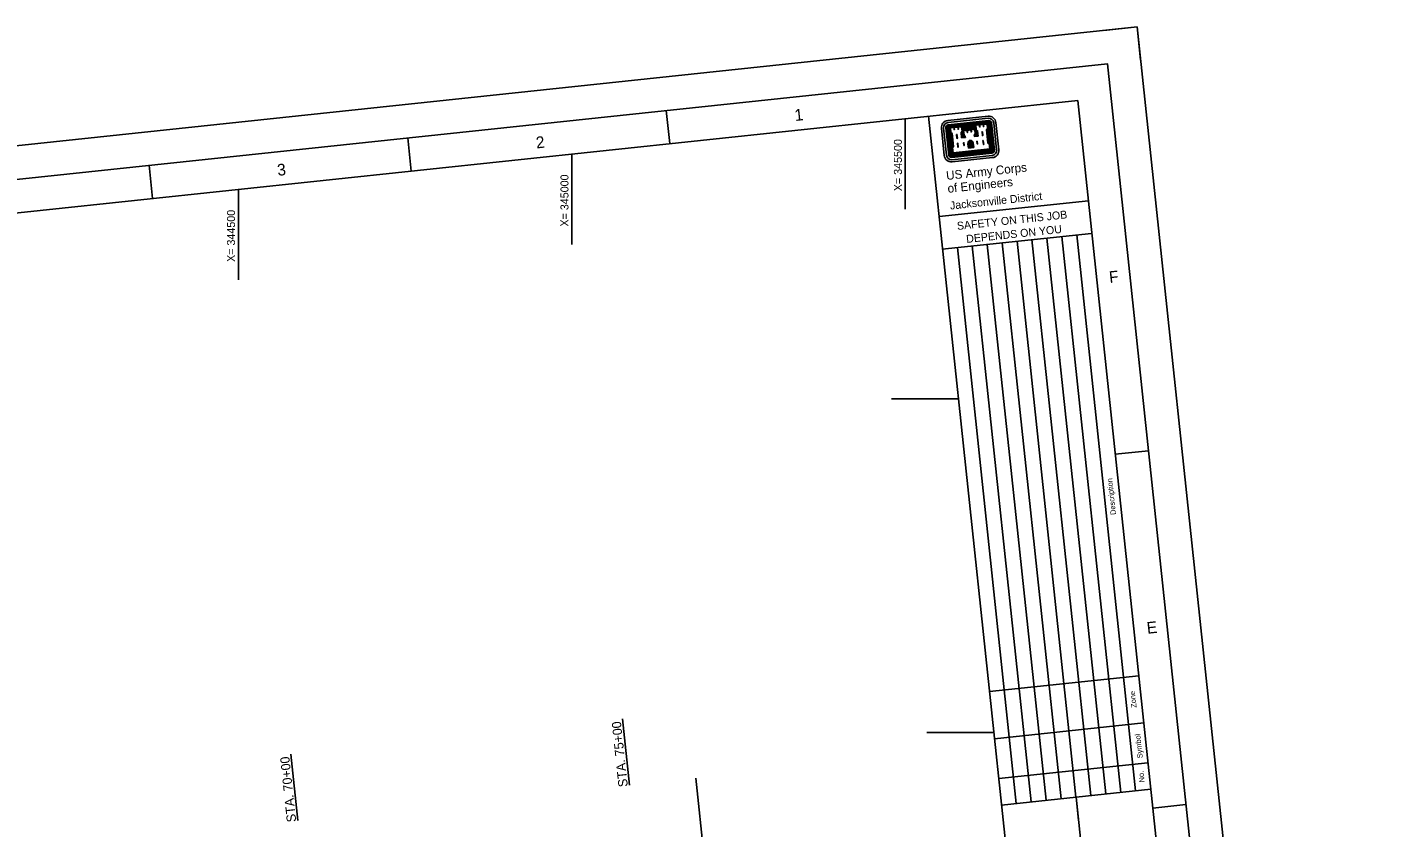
# Model space of a CAD drawing. Extents: x 341472 to 346206, y 1184213 to 1188058.
# Drawn here: x 344183 to 346206, y 1186858 to 1188058 of the extents above; entities that cross this region are included whole.
import ezdxf

# ---------------------------------------------------------------- set-up
doc = ezdxf.new("R2010")
doc.units = 0
for name, color, linetype in [('G-ANNO-NPLT', 7, 'Continuous'), ('G-ANNO-TEXT-LOGO', 7, 'Continuous'), ('G-ANNO-TEXT-TTLB', 7, 'Continuous'), ('G-ANNO-TTLB', 7, 'Continuous'), ('V-ALGN-TEXT', 7, 'Continuous'), ('V-ANNO-MATC', 7, 'Continuous'), ('V-TOPO-COOR-STAT', 7, 'Continuous')]:
    doc.layers.add(name, color=color, linetype=linetype)

msp = doc.modelspace()

# ---------------------------------------------------------------- linework, layer by layer
at = {"layer": 'G-ANNO-NPLT'}
msp.add_lwpolyline([(341472, 1187593.7), (345847.5, 1188057.5), (346205.9, 1184676.5), (341830.4, 1184212.7)], close=True, dxfattribs=at)
msp.add_lwpolyline([(345852.7, 1188007.8), (345847.5, 1188057.5), (345797.8, 1188052.2)], dxfattribs=at)
at = {"layer": 'G-ANNO-TEXT-LOGO'}
for p, q in [((345624.2, 1187923.8), (345563.7, 1187917.4)), ((345564.1, 1187914.2), (345624.5, 1187920.7)), ((345624.9, 1187917.3), (345564.4, 1187910.9)), ((345625, 1187916.4), (345564.5, 1187910)), ((345625.1, 1187915.5), (345564.6, 1187909.1)), ((345625.1, 1187914.7), (345564.7, 1187908.3)), ((345625.2, 1187913.8), (345564.8, 1187907.4)), ((345624.1, 1187913.1), (345628.3, 1187873.5)), ((345624.9, 1187913.2), (345629.2, 1187872.7)), ((345625.8, 1187913.3), (345630.1, 1187872.5)), ((345626.7, 1187913.3), (345631, 1187872.6)), ((345627.5, 1187913.4), (345631.8, 1187872.7)), ((345628.4, 1187913.5), (345632.7, 1187872.8)), ((345629.3, 1187913.6), (345633.6, 1187872.8)), ((345632.7, 1187914), (345637, 1187873.2)), ((345640.3, 1187873.6), (345635.9, 1187914.3)), ((345554.2, 1187905.7), (345558.5, 1187864.9)), ((345561.7, 1187865.2), (345557.4, 1187906)), ((345560.9, 1187906.4), (345565.2, 1187865.6)), ((345561.8, 1187906.5), (345566.1, 1187865.7)), ((345562.6, 1187906.5), (345566.9, 1187865.8)), ((345563.5, 1187906.6), (345567.8, 1187865.9)), ((345564.3, 1187906.7), (345568.7, 1187866)), ((345565.2, 1187906.8), (345569.5, 1187866.4)), ((345566, 1187906.9), (345570.2, 1187867.3)), ((345567.7, 1187898.3), (345569.9, 1187877.5)), ((345568.6, 1187897.5), (345570.7, 1187878.5)), ((345585.8, 1187908.8), (345604.3, 1187910.8)), ((345585.9, 1187907.9), (345604.4, 1187909.9)), ((345586, 1187907.1), (345604.5, 1187909.1)), ((345586.1, 1187906.2), (345604.6, 1187908.2)), ((345586.2, 1187905.3), (345604.7, 1187907.3)), ((345586.3, 1187904.5), (345604.8, 1187906.5)), ((345586.4, 1187903.6), (345604.9, 1187905.6)), ((345623.5, 1187903.4), (345625.5, 1187884.4)), ((345624.3, 1187904.2), (345626.5, 1187883.6)), ((345629.7, 1187871.8), (345569.2, 1187865.4)), ((345629.8, 1187871), (345569.3, 1187864.6)), ((345629.2, 1187872.7), (345569.5, 1187866.4)), ((345628.3, 1187873.5), (345570.2, 1187867.3)), ((345594.7, 1187875.9), (345594, 1187882.5)), ((345594.7, 1187875.9), (345602.6, 1187876.7)), ((345595.5, 1187875.9), (345594.8, 1187882.6)), ((345596.4, 1187876), (345595.7, 1187882.7)), ((345597.3, 1187876.1), (345596.6, 1187882.8)), ((345598.1, 1187876.2), (345597.3, 1187882.9)), ((345599.2, 1187876.3), (345598.5, 1187883)), ((345600, 1187876.4), (345599.3, 1187883.1)), ((345600.9, 1187876.5), (345600.2, 1187883.2)), ((345601.8, 1187876.6), (345601.1, 1187883.3)), ((345602.6, 1187876.7), (345601.9, 1187883.4)), ((345629.9, 1187870.1), (345569.4, 1187863.7)), ((345630, 1187869.2), (345569.5, 1187862.8)), ((345630.1, 1187868.4), (345569.6, 1187862)), ((345630.4, 1187865), (345570, 1187858.6)), ((345570.3, 1187855.3), (345630.8, 1187861.7))]:
    msp.add_line(p, q, dxfattribs=at)
for points in [[(345566.7, 1187907), (345567.6, 1187899.1), (345569.4, 1187897.6), (345571.5, 1187878.6), (345570, 1187876.7), (345570.9, 1187868), (345627.5, 1187874), (345626.6, 1187882.7), (345624.7, 1187884.3), (345622.6, 1187903.3), (345624.3, 1187905.1), (345623.4, 1187913), (345616, 1187912.2), (345610.2, 1187911.6), (345604.8, 1187911), (345605.7, 1187903.2), (345607.7, 1187901.7), (345608.5, 1187894.7), (345604.3, 1187894.3), (345604.2, 1187895), (345605.8, 1187897), (345605, 1187904.7), (345597.5, 1187903.9), (345591.8, 1187903.3), (345586.5, 1187902.7), (345587.3, 1187895), (345589.3, 1187893.4), (345589.4, 1187892.7), (345585.2, 1187892.3), (345584.5, 1187899.2), (345586.1, 1187901.1), (345585.2, 1187908.9), (345577.8, 1187908.2), (345572, 1187907.5), (345566.7, 1187907)], [(345567.6, 1187906.2), (345568.3, 1187899.6), (345570.3, 1187898), (345572.4, 1187878.3), (345570.8, 1187876.3), (345571.6, 1187869), (345626.7, 1187874.8), (345625.9, 1187882.2), (345623.8, 1187883.8), (345621.7, 1187903.5), (345623.4, 1187905.5), (345622.7, 1187912), (345617.3, 1187911.4), (345617.7, 1187908.4), (345617.2, 1187908.3), (345616.9, 1187911.4), (345611.6, 1187910.8), (345611.9, 1187907.8), (345611.5, 1187907.7), (345611.2, 1187910.8), (345605.8, 1187910.2), (345606.5, 1187903.7), (345608.5, 1187902.1), (345609.3, 1187894), (345603.6, 1187893.4), (345603.4, 1187895.3), (345605, 1187897.3), (345604.3, 1187903.8), (345598.9, 1187903.3), (345599.2, 1187900.2), (345598.8, 1187900.1), (345598.5, 1187903.2), (345593.1, 1187902.6), (345593.5, 1187899.6), (345593, 1187899.5), (345592.6, 1187902.6), (345587.4, 1187902), (345588.1, 1187895.5), (345590, 1187893.9), (345590.2, 1187892), (345584.5, 1187891.4), (345583.6, 1187899.4), (345585.2, 1187901.4), (345584.5, 1187908), (345579.3, 1187907.4), (345579.6, 1187904.3), (345579.1, 1187904.3), (345578.8, 1187907.4), (345573.4, 1187906.8), (345573.7, 1187903.7), (345573.3, 1187903.7), (345573, 1187906.7), (345567.6, 1187906.2)], [(345576.9, 1187896.4), (345577.5, 1187890.6), (345578.1, 1187890.7), (345577.5, 1187896.5), (345576.9, 1187896.4)], [(345585.8, 1187899.5), (345585.4, 1187898.9), (345586, 1187893.2), (345587.9, 1187893.4), (345586.5, 1187894.6), (345585.9, 1187899.6)], [(345606.3, 1187901.6), (345606.9, 1187901.2), (345607.5, 1187895.5), (345605.7, 1187895.3), (345606.7, 1187896.7), (345606.2, 1187901.7)], [(345615.6, 1187900.5), (345616.2, 1187894.7), (345615.7, 1187894.7), (345615.1, 1187900.4), (345615.6, 1187900.5)], [(345578.3, 1187883.2), (345578.9, 1187877.3), (345579.5, 1187877.4), (345578.9, 1187883.2), (345578.3, 1187883.2)], [(345587.5, 1187884.1), (345587.9, 1187880.1), (345588.4, 1187880.1), (345588, 1187884.2), (345587.5, 1187884.1)], [(345607.9, 1187886.3), (345608.4, 1187882.2), (345607.9, 1187882.2), (345607.4, 1187886.3), (345607.9, 1187886.3)], [(345617, 1187887.3), (345617.6, 1187881.4), (345617.1, 1187881.4), (345616.5, 1187887.2), (345617, 1187887.3)]]:
    msp.add_lwpolyline(points, dxfattribs=at)
for centre, major_axis, start_param, end_param in [((345564.9, 1187906.8), (10.7, 1.1), 1.57078, 3.141576), ((345564.9, 1187906.8), (7.45, 0.79), 1.57078, 3.141576), ((345625.2, 1187913.2), (10.7, 1.1), 6.283169, 7.853965), ((345625.2, 1187913.2), (7.45, 0.79), 6.28317, 7.853966), ((345625.2, 1187913.2), (4, 0.42), 6.283169, 7.853965), ((345625.2, 1187913.2), (3.13, 0.33), 6.283169, 7.853965), ((345625.2, 1187913.2), (2.27, 0.24), 6.283169, 7.853965), ((345625.2, 1187913.2), (1.41, 0.15), 6.283169, 7.853965), ((345625.2, 1187913.2), (0.543, 0.058), 6.283169, 7.853965), ((345564.9, 1187906.8), (4, 0.42), 1.57078, 3.141576), ((345564.9, 1187906.8), (3.13, 0.33), 1.57078, 3.141576), ((345564.9, 1187906.8), (2.27, 0.24), 1.57078, 3.141576), ((345564.9, 1187906.8), (1.41, 0.15), 1.57078, 3.141576), ((345564.9, 1187906.8), (0.543, 0.058), 1.57078, 3.141576), ((345599.5, 1187882.7), (-5.52, -0.59), 4.985832, 6.214359), ((345599.5, 1187882.7), (-4.66, -0.49), 4.947465, 6.21436), ((345599.5, 1187882.7), (-3.8, -0.4), 4.947465, 6.21436), ((345599.5, 1187882.7), (-2.93, -0.31), 4.947465, 6.21436), ((345596.5, 1187882.3), (2.07, 0.22), 0.068794, 1.335689), ((345596.5, 1187882.3), (2.93, 0.31), 0.068794, 1.335689), ((345596.5, 1187882.3), (3.8, 0.4), 0.068795, 1.335689), ((345596.5, 1187882.3), (4.66, 0.49), 0.068795, 1.335689), ((345599.5, 1187882.7), (-2.07, -0.22), 4.947465, 6.214359), ((345596.5, 1187882.3), (5.52, 0.59), 0.068795, 1.29842), ((345629.6, 1187872.4), (0.543, 0.058), 4.712373, 6.28317), ((345629.6, 1187872.4), (1.41, 0.15), 4.712373, 6.28317), ((345629.6, 1187872.4), (2.27, 0.24), 4.712373, 6.28317), ((345629.6, 1187872.4), (3.13, 0.33), 4.712373, 6.28317), ((345629.6, 1187872.4), (4, 0.42), 4.712373, 6.28317), ((345629.6, 1187872.4), (-7.45, -0.79), 1.570781, 3.141577), ((345629.6, 1187872.4), (10.7, 1.1), 4.712373, 6.28317), ((345569.2, 1187866), (-10.7, -1.1), 6.28317, 7.853966), ((345569.2, 1187866), (-7.45, -0.79), 6.28317, 7.853966), ((345569.2, 1187866), (-4, -0.42), 6.28317, 7.853966), ((345569.2, 1187866), (-3.13, -0.33), 6.28317, 7.853966), ((345569.2, 1187866), (-2.27, -0.24), 6.28317, 7.853966), ((345569.2, 1187866), (-1.41, -0.15), 6.28317, 7.853966), ((345569.2, 1187866), (-0.543, -0.058), 6.28317, 7.853966)]:
    msp.add_ellipse(centre, major_axis=major_axis, ratio=0.99964, start_param=start_param, end_param=end_param, dxfattribs=at)
at = {"layer": 'G-ANNO-TTLB'}
for p, q in [((345141.7, 1187932.4), (345147, 1187882.7)), ((345534.8, 1187923.8), (345872.1, 1184741.6)), ((344753.9, 1187891.3), (344759.2, 1187841.6)), ((344366.1, 1187850.2), (344371.4, 1187800.5)), ((345550.8, 1187773.4), (345774.5, 1187797.1)), ((345555.3, 1187724.5), (345779.1, 1187748.2)), ((345600.5, 1187729.3), (345688.8, 1186896)), ((345622.9, 1187731.7), (345711.2, 1186898.4)), ((345645.3, 1187734), (345733.6, 1186900.8)), ((345667.6, 1187736.4), (345756, 1186903.2)), ((345690, 1187738.8), (345778.3, 1186905.5)), ((345712.4, 1187741.2), (345800.7, 1186907.9)), ((345734.8, 1187743.5), (345823.1, 1186910.3)), ((345757.1, 1187745.9), (345845.4, 1186912.6)), ((345578.1, 1187726.9), (345666.5, 1186893.7)), ((345864.5, 1187422.3), (345814.8, 1187417)), ((345626.2, 1187061.4), (345850, 1187085.1)), ((345633.7, 1186990.6), (345857.5, 1187014.3)), ((345640.1, 1186931), (345863.8, 1186954.6)), ((345644.3, 1186891.3), (345868, 1186915)), ((345846.1, 1186048.3), (345756.1, 1186903.2)), ((345756.1, 1186903.2), (345759.8, 1186868)), ((345920.7, 1186891.9), (345871, 1186886.7))]:
    msp.add_line(p, q, dxfattribs=at)
for points in [[(341874.8, 1184267.7), (346150.9, 1184720.9), (345803, 1188002.5), (341527, 1187549.3)], [(345758.6, 1187947.5), (341656.6, 1187512.7), (341993.9, 1184330.6), (346095.9, 1184765.4)]]:
    msp.add_lwpolyline(points, close=True, dxfattribs=at)
at = {"layer": 'V-ALGN-TEXT'}
for p, q in [((345086.6, 1186921), (345076.1, 1187020.4)), ((344589.4, 1186868.3), (344578.9, 1186967.7))]:
    msp.add_line(p, q, dxfattribs=at)
at = {"layer": 'V-ANNO-MATC'}
msp.add_line((345323.1, 1185638.8), (345186.1, 1186931.5), dxfattribs=at)
at = {"layer": 'V-TOPO-COOR-STAT'}
for p, q in [((345500, 1187784.4), (345500, 1187920.1)), ((345000, 1187731.4), (345000, 1187867.1)), ((344500, 1187678.4), (344500, 1187814.1)), ((345479.2, 1187500), (345579.7, 1187500)), ((345532.2, 1187000), (345632.7, 1187000))]:
    msp.add_line(p, q, dxfattribs=at)

# ---------------------------------------------------------------- texts
at = {"layer": 'G-ANNO-TEXT-TTLB'}
for s, height, rotation, p in [('US Army Corps', 13.086, 6.0506, (345562, 1187828.2)), ('of Engineers', 13.086, 6.0506, (345564.1, 1187808.9)), ('Jacksonville District', 11.9, 6.0506, (345567.7, 1187783.8)), ('SAFETY ON THIS JOB', 11.9, 6.0506, (345578.1, 1187753.3)), ('DEPENDS ON YOU', 11.9, 6.0506, (345592, 1187733.8)), ('Description', 8, 96.0506, (345816, 1187326.6)), ('Zone', 8, 96.0506, (345846.9, 1187037.5)), ('Symbol', 8, 96.0506, (345856.1, 1186961.8)), ('No.', 8, 96.0506, (345858.9, 1186925.7))]:
    msp.add_text(s, height=height, rotation=rotation, dxfattribs=at).set_placement(p)
at = {"layer": 'G-ANNO-TTLB'}
for s, p in [('1', (345334.9, 1187916.5)), ('2', (344947.1, 1187875.4)), ('3', (344559.2, 1187834.3)), ('F', (345806.5, 1187673.7)), ('E', (345863, 1187147.9))]:
    msp.add_text(s, height=17.5, rotation=6.0506, dxfattribs=at).set_placement(p)
at = {"layer": 'V-ALGN-TEXT'}
for s, p in [('STA. 75+00', (345084, 1186919)), ('STA. 70+00', (344586.8, 1186866.3))]:
    msp.add_text(s, height=13.92, rotation=96.0506, dxfattribs=at).set_placement(p)
at = {"layer": 'V-TOPO-COOR-STAT'}
for s, p in [('X= 345500', (345495, 1187811.4)), ('X= 345000', (344995, 1187758.4)), ('X= 344500', (344495, 1187705.4))]:
    msp.add_text(s, height=12, rotation=90, dxfattribs=at).set_placement(p)

doc.saveas('drawing.dxf')
